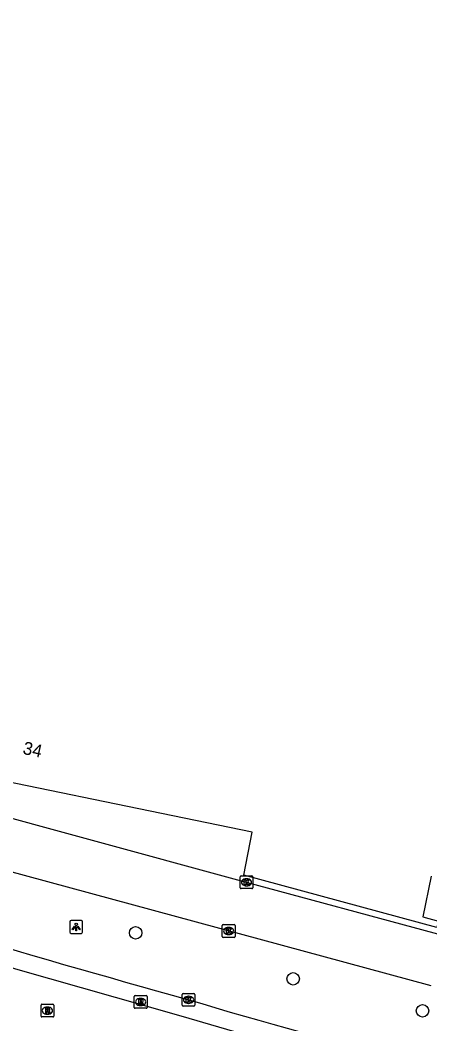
# Model space of a CAD drawing. Extents: x 157692 to 159670, y 381454 to 383289.
# Drawn here: x 158212.4 to 158244.4, y 382767.5 to 382846.1 of the extents above; entities that cross this region are included whole.
import ezdxf

# ---------------------------------------------------------------- set-up
doc = ezdxf.new("R2010")
doc.units = 0
for name, color, linetype in [('IMGEO_Boom', 7, 'Continuous'), ('IMGEO_Kolk', 7, 'Continuous'), ('IMGEO_Lichtpunt', 7, 'Continuous'), ('IMGEO_Pand', 7, 'Continuous'), ('IMGEO_Pand_nummerreeks', 7, 'Continuous'), ('IMGEO_Rijbaan_lokaal_gesloten', 7, 'Continuous'), ('IMGEO_Rijbaan_lokaal_open', 7, 'Continuous'), ('IMGEO_Rioolput', 7, 'Continuous')]:
    doc.layers.add(name, color=color, linetype=linetype)

msp = doc.modelspace()

# ---------------------------------------------------------------- linework, layer by layer
at = {"layer": 'IMGEO_Boom'}
for centre in [(158221.406, 382774.591), (158233.732, 382770.993), (158243.864, 382768.483)]:
    msp.add_circle(centre, 0.489, dxfattribs=at)
at = {"layer": 'IMGEO_Kolk'}
for p, q in [((158229.583, 382778.127), (158229.583, 382778.979)), ((158229.658, 382779.053), (158230.51, 382779.053)), ((158230.071, 382778.833), (158230.096, 382778.833)), ((158230.584, 382778.979), (158230.584, 382778.127)), ((158230.51, 382778.053), (158229.658, 382778.053)), ((158230.094, 382778.273), (158230.069, 382778.273)), ((158228.186, 382774.31), (158228.186, 382775.162)), ((158228.261, 382775.236), (158229.113, 382775.236)), ((158228.674, 382775.016), (158228.699, 382775.016)), ((158229.187, 382775.162), (158229.187, 382774.31)), ((158229.113, 382774.236), (158228.261, 382774.236)), ((158228.697, 382774.456), (158228.672, 382774.456)), ((158225.045, 382768.919), (158225.045, 382769.771)), ((158225.12, 382769.845), (158225.972, 382769.845)), ((158225.533, 382769.625), (158225.558, 382769.625)), ((158226.046, 382769.771), (158226.046, 382768.919)), ((158225.972, 382768.845), (158225.12, 382768.845)), ((158225.556, 382769.065), (158225.531, 382769.065))]:
    msp.add_line(p, q, dxfattribs=at)
for points in [[(158229.583, 382778.127), (158229.583, 382778.979)], [(158229.658, 382779.053), (158230.51, 382779.053)], [(158230.584, 382778.979), (158230.584, 382778.127)], [(158230.51, 382778.053), (158229.658, 382778.053)], [(158229.904, 382778.753), (158230.027, 382778.753), (158230.027, 382778.602), (158230.157, 382778.753), (158230.321, 382778.753), (158230.175, 382778.602), (158230.328, 382778.353), (158230.176, 382778.353), (158230.091, 382778.517), (158230.027, 382778.45), (158230.027, 382778.353), (158229.904, 382778.353), (158229.904, 382778.753)], [(158228.186, 382774.31), (158228.186, 382775.162)], [(158228.261, 382775.236), (158229.113, 382775.236)], [(158228.507, 382774.936), (158228.63, 382774.936), (158228.63, 382774.785), (158228.76, 382774.936), (158228.924, 382774.936), (158228.778, 382774.785), (158228.931, 382774.536), (158228.779, 382774.536), (158228.694, 382774.7), (158228.63, 382774.633), (158228.63, 382774.536), (158228.507, 382774.536), (158228.507, 382774.936)], [(158229.187, 382775.162), (158229.187, 382774.31)], [(158229.113, 382774.236), (158228.261, 382774.236)], [(158225.045, 382768.919), (158225.045, 382769.771)], [(158225.12, 382769.845), (158225.972, 382769.845)], [(158225.366, 382769.545), (158225.489, 382769.545), (158225.489, 382769.394), (158225.619, 382769.545), (158225.783, 382769.545), (158225.637, 382769.394), (158225.79, 382769.145), (158225.638, 382769.145), (158225.553, 382769.309), (158225.489, 382769.242), (158225.489, 382769.145), (158225.366, 382769.145), (158225.366, 382769.545)], [(158226.046, 382769.771), (158226.046, 382768.919)], [(158225.972, 382768.845), (158225.12, 382768.845)]]:
    msp.add_lwpolyline(points, dxfattribs=at)
for centre, start, end in [((158229.66, 382778.977), 91.55205, 178.44795), ((158229.66, 382778.977), 91.55205, 178.44795), ((158230.508, 382778.977), 1.55205, 88.44795), ((158230.508, 382778.977), 1.55205, 88.44795), ((158229.66, 382778.129), 181.55205, 268.44795), ((158229.66, 382778.129), 181.55205, 268.44795), ((158230.508, 382778.129), 271.55205, 358.44795), ((158230.508, 382778.129), 271.55205, 358.44795), ((158228.263, 382775.16), 91.55205, 178.44795), ((158228.263, 382775.16), 91.55205, 178.44795), ((158229.111, 382775.16), 1.55205, 88.44795), ((158229.111, 382775.16), 1.55205, 88.44795), ((158228.263, 382774.312), 181.55205, 268.44795), ((158228.263, 382774.312), 181.55205, 268.44795), ((158229.111, 382774.312), 271.55205, 358.44795), ((158229.111, 382774.312), 271.55205, 358.44795), ((158225.122, 382769.769), 91.55205, 178.44795), ((158225.122, 382769.769), 91.55205, 178.44795), ((158225.97, 382769.769), 1.55205, 88.44795), ((158225.97, 382769.769), 1.55205, 88.44795), ((158225.122, 382768.921), 181.55205, 268.44795), ((158225.122, 382768.921), 181.55205, 268.44795), ((158225.97, 382768.921), 271.55205, 358.44795), ((158225.97, 382768.921), 271.55205, 358.44795)]:
    msp.add_arc(centre, 0.0765, start, end, dxfattribs=at)
for centre, major_axis, ratio, start_param, end_param in [((158230.07, 382778.553), (-0.387, 0.002), 0.722429, 4.712389, 7.853982), ((158230.095, 382778.553), (-0.39, 0.002), 0.717154, 1.570796, 4.712389), ((158228.673, 382774.736), (-0.387, 0.002), 0.722429, 4.712389, 7.853982), ((158228.698, 382774.736), (-0.39, 0.002), 0.717154, 1.570796, 4.712389), ((158225.532, 382769.345), (-0.387, 0.002), 0.722429, 4.712389, 7.853982), ((158225.557, 382769.345), (-0.39, 0.002), 0.717154, 1.570796, 4.712389)]:
    msp.add_ellipse(centre, major_axis=major_axis, ratio=ratio, start_param=start_param, end_param=end_param, dxfattribs=at)
at = {"layer": 'IMGEO_Lichtpunt'}
for p, q in [((158216.256, 382775.454), (158216.256, 382774.647)), ((158216.256, 382775.454), (158216.256, 382774.647)), ((158217.158, 382775.549), (158216.35, 382775.549)), ((158217.158, 382775.549), (158216.35, 382775.549)), ((158217.252, 382774.647), (158217.252, 382775.454)), ((158217.252, 382774.647), (158217.252, 382775.454)), ((158216.35, 382774.553), (158217.158, 382774.553)), ((158216.35, 382774.553), (158217.158, 382774.553))]:
    msp.add_line(p, q, dxfattribs=at)
for points in [[(158216.63, 382775.118), (158216.669, 382775.09), (158216.481, 382774.828), (158216.443, 382774.855), (158216.63, 382775.118)], [(158216.732, 382775.07), (158216.779, 382775.07), (158216.779, 382774.748), (158216.732, 382774.748), (158216.732, 382775.07)], [(158216.842, 382775.09), (158216.88, 382775.117), (158217.067, 382774.855), (158217.028, 382774.827), (158216.842, 382775.09)]]:
    msp.add_lwpolyline(points, dxfattribs=at)
msp.add_circle((158216.755, 382775.252), 0.0994, dxfattribs=at)
for centre, start, end in [((158216.35, 382775.454), 90, 180), ((158216.35, 382775.454), 90, 180), ((158217.158, 382775.454), 0, 90), ((158217.158, 382775.454), 0, 90), ((158216.35, 382774.647), 180, 270), ((158216.35, 382774.647), 180, 270), ((158217.158, 382774.647), 270, 0), ((158217.158, 382774.647), 270, 360)]:
    msp.add_arc(centre, 0.0946, start, end, dxfattribs=at)
at = {"layer": 'IMGEO_Pand'}
msp.add_lwpolyline([(158244.537, 382779.018), (158243.882, 382775.836), (158245.101, 382775.518), (158244.971, 382775.019), (158229.866, 382779.104), (158230.532, 382782.482), (158203.138, 382788.103), (158197.657, 382789.345), (158192.235, 382790.763), (158186.853, 382792.354), (158181.395, 382794.161), (158180.601, 382794.438), (158180.702, 382794.926), (158181.486, 382794.763), (158181.89, 382796.739), (158185.9, 382816.356), (158185.179, 382816.504)], dxfattribs=at)
at = {"layer": 'IMGEO_Rijbaan_lokaal_gesloten'}
msp.add_lwpolyline([(158286.514, 382753.477), (158260.379, 382758.975), (158254.227, 382760.339), (158248.354, 382761.725), (158242.501, 382763.187), (158236.667, 382764.728), (158230.854, 382766.346), (158224.966, 382768.069), (158212.034, 382771.752), (158186.42, 382779.71), (158168.446, 382786.031), (158150.232, 382793.099), (158135.179, 382799.369), (158132.175, 382800.62), (158132.064, 382800.666), (158127.783, 382802.635), (158116.454, 382807.771), (158101.276, 382815.071), (158086.186, 382822.743), (158068.81, 382832.394), (158056.432, 382839.751), (158045.401, 382846.414), (158021.35, 382861.883), (158020.199, 382862.608)], dxfattribs=at)
for centre, radius, start, end in [((158451.624, 383588.09), 849.37, 251.837588, 254.557866), ((158355.405, 383202.561), 452.248, 253.30257, 258.00905)]:
    msp.add_arc(centre, radius, start, end, dxfattribs=at)
at = {"layer": 'IMGEO_Rijbaan_lokaal_open'}
for points in [[(158179.985, 382792.666), (158197.22, 382787.5), (158229.096, 382778.81), (158245.717, 382774.327), (158246.692, 382774.123)], [(158244.525, 382770.452), (158196.142, 382783.579), (158176.093, 382789.592)]]:
    msp.add_lwpolyline(points, dxfattribs=at)
at = {"layer": 'IMGEO_Rioolput'}
for p, q in [((158221.294, 382768.756), (158221.294, 382769.608)), ((158221.369, 382769.682), (158222.221, 382769.682)), ((158221.782, 382769.462), (158221.807, 382769.462)), ((158222.295, 382769.608), (158222.295, 382768.756)), ((158213.999, 382768.078), (158213.999, 382768.93)), ((158214.074, 382769.004), (158214.926, 382769.004)), ((158214.487, 382768.784), (158214.512, 382768.784)), ((158215, 382768.93), (158215, 382768.078)), ((158222.221, 382768.682), (158221.369, 382768.682)), ((158221.805, 382768.902), (158221.78, 382768.902)), ((158214.926, 382768.004), (158214.074, 382768.004)), ((158214.51, 382768.224), (158214.485, 382768.224))]:
    msp.add_line(p, q, dxfattribs=at)
for points in [[(158221.294, 382768.756), (158221.294, 382769.608)], [(158221.369, 382769.682), (158222.221, 382769.682)], [(158221.883, 382769.38), (158221.631, 382769.382), (158221.631, 382768.982)], [(158222.295, 382769.608), (158222.295, 382768.756)], [(158213.999, 382768.078), (158213.999, 382768.93)], [(158214.074, 382769.004), (158214.926, 382769.004)], [(158214.588, 382768.702), (158214.336, 382768.704), (158214.336, 382768.304)], [(158214.514, 382768.623), (158214.46, 382768.623), (158214.46, 382768.542)], [(158215, 382768.93), (158215, 382768.078)], [(158222.221, 382768.682), (158221.369, 382768.682)], [(158221.631, 382768.982), (158221.755, 382768.982), (158221.755, 382769.144), (158221.766, 382769.144)], [(158221.809, 382769.301), (158221.755, 382769.301), (158221.755, 382769.22)], [(158221.755, 382769.22), (158221.807, 382769.22)], [(158221.813, 382769.115), (158221.884, 382768.982), (158222.024, 382768.982), (158221.959, 382769.108)], [(158214.926, 382768.004), (158214.074, 382768.004)], [(158214.336, 382768.304), (158214.46, 382768.304), (158214.46, 382768.466), (158214.471, 382768.466)], [(158214.46, 382768.542), (158214.512, 382768.542)], [(158214.518, 382768.437), (158214.589, 382768.304), (158214.729, 382768.304), (158214.664, 382768.43)]]:
    msp.add_lwpolyline(points, dxfattribs=at)
for centre, radius, start, end in [((158221.371, 382769.606), 0.0765, 91.55205, 178.44795), ((158221.371, 382769.606), 0.0765, 91.55205, 178.44795), ((158221.882, 382769.27), 0.109, 350.36119, 89.41601), ((158222.219, 382769.606), 0.0765, 1.55205, 88.44795), ((158222.219, 382769.606), 0.0765, 1.55205, 88.44795), ((158214.076, 382768.928), 0.0765, 91.55205, 178.44795), ((158214.076, 382768.928), 0.0765, 91.55205, 178.44795), ((158214.52, 382768.527), 0.0964, 77.00612, 93.18647), ((158214.534, 382768.584), 0.0378, 276.66336, 79.67722), ((158214.587, 382768.592), 0.109, 350.36119, 89.41601), ((158214.585, 382768.592), 0.112, 277.58423, 350.98172), ((158214.924, 382768.928), 0.0765, 1.55205, 88.44795), ((158214.924, 382768.928), 0.0765, 1.55205, 88.44795), ((158221.371, 382768.758), 0.0765, 181.55205, 268.44795), ((158221.371, 382768.758), 0.0765, 181.55205, 268.44795), ((158221.765, 382769.091), 0.0533, 26.02933, 88.69889), ((158221.791, 382769.409), 0.19, 274.7715, 282.96867), ((158221.815, 382769.205), 0.0964, 77.00612, 93.18647), ((158221.829, 382769.262), 0.0378, 276.66336, 79.67722), ((158221.88, 382769.27), 0.112, 277.58423, 350.98172), ((158221.864, 382769.055), 0.108, 29.51342, 73.79051), ((158222.219, 382768.758), 0.0765, 271.55205, 358.44795), ((158222.219, 382768.758), 0.0765, 271.55205, 358.44795), ((158214.076, 382768.08), 0.0765, 181.55205, 268.44795), ((158214.076, 382768.08), 0.0765, 181.55205, 268.44795), ((158214.47, 382768.413), 0.0533, 26.02933, 88.69889), ((158214.496, 382768.731), 0.19, 274.7715, 282.96867), ((158214.569, 382768.377), 0.108, 29.51342, 73.79051), ((158214.924, 382768.08), 0.0765, 271.55205, 358.44795), ((158214.924, 382768.08), 0.0765, 271.55205, 358.44795)]:
    msp.add_arc(centre, radius, start, end, dxfattribs=at)
for centre, major_axis, ratio, start_param, end_param in [((158221.781, 382769.182), (-0.387, 0.002), 0.722429, 4.712389, 7.853982), ((158221.806, 382769.182), (-0.39, 0.002), 0.717154, 1.570796, 4.712389), ((158214.486, 382768.504), (-0.387, 0.002), 0.722429, 4.712389, 7.853982), ((158214.511, 382768.504), (-0.39, 0.002), 0.717154, 1.570796, 4.712389)]:
    msp.add_ellipse(centre, major_axis=major_axis, ratio=ratio, start_param=start_param, end_param=end_param, dxfattribs=at)

# ---------------------------------------------------------------- texts
at = {"layer": 'IMGEO_Pand_nummerreeks'}
msp.add_text('34', height=1, rotation=347.59546, dxfattribs=at).set_placement((158212.513, 382788.616))

doc.saveas('drawing.dxf')
